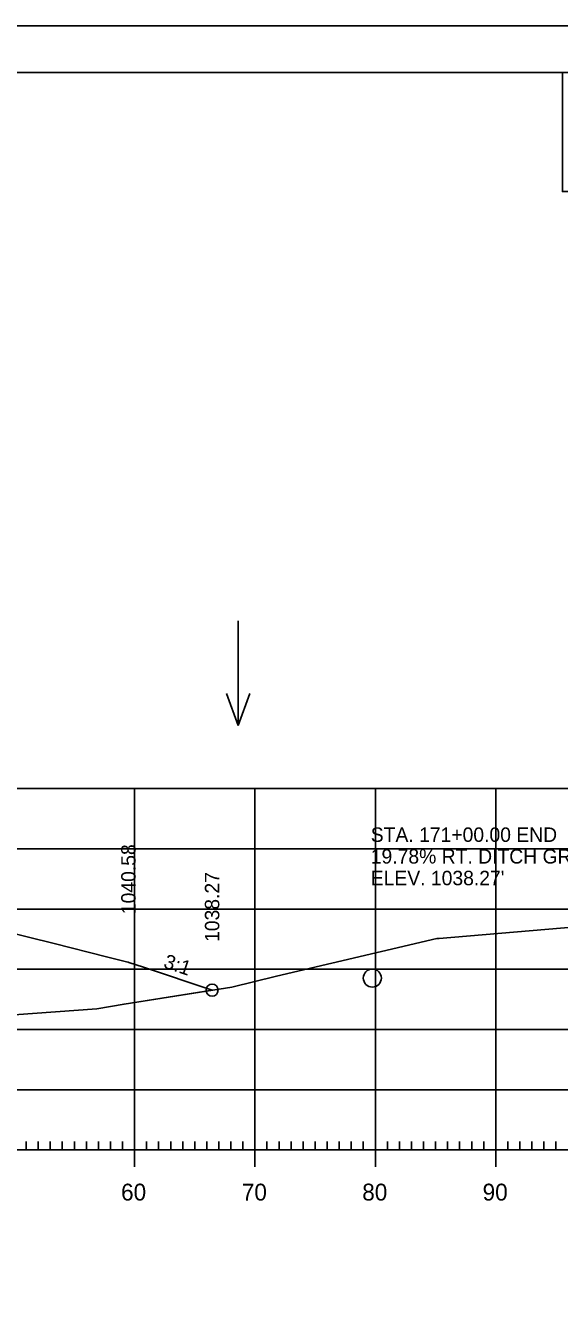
# Model space of a CAD drawing. Extents: x 1322838 to 1324533, y 339903 to 351025.
# Drawn here: x 1323754.7 to 1323799, y 347078.5 to 347185.2 of the extents above; entities that cross this region are included whole.
import ezdxf

# ---------------------------------------------------------------- set-up
doc = ezdxf.new("R2010")
doc.units = 0
for name, color, linetype in [('R_Axis', 7, 'Continuous'), ('R_Axis Annot', 7, 'Continuous'), ('R_Border', 7, 'Continuous'), ('R_Drive', 7, 'Continuous'), ('R_Exist Surface', 7, 'Continuous'), ('R_Fin Surface', 7, 'Continuous'), ('R_Fin Surface Annot', 7, 'Continuous'), ('R_Grid', 7, 'Continuous'), ('R_No Plot', 7, 'Continuous'), ('R_Water', 7, 'Continuous'), ('R_Water Annot', 7, 'Continuous')]:
    doc.layers.add(name, color=color, linetype=linetype)

msp = doc.modelspace()

# ---------------------------------------------------------------- linework, layer by layer
at = {"layer": 'R_Axis'}
for p, q in [((1323763.72, 347090.44), (1323763.72, 347093.24)), ((1323773.72, 347090.44), (1323773.72, 347093.24)), ((1323783.72, 347090.44), (1323783.72, 347093.24)), ((1323793.72, 347090.44), (1323793.72, 347093.24)), ((1323563.72, 347091.84), (1323843.72, 347091.84)), ((1323754.72, 347091.84), (1323754.72, 347092.54)), ((1323755.72, 347091.84), (1323755.72, 347092.54)), ((1323756.72, 347091.84), (1323756.72, 347092.54)), ((1323757.72, 347091.84), (1323757.72, 347092.54)), ((1323758.72, 347091.84), (1323758.72, 347092.54)), ((1323759.72, 347091.84), (1323759.72, 347092.54)), ((1323760.72, 347091.84), (1323760.72, 347092.54)), ((1323761.72, 347091.84), (1323761.72, 347092.54)), ((1323762.72, 347091.84), (1323762.72, 347092.54)), ((1323764.72, 347091.84), (1323764.72, 347092.54)), ((1323765.72, 347091.84), (1323765.72, 347092.54)), ((1323766.72, 347091.84), (1323766.72, 347092.54)), ((1323767.72, 347091.84), (1323767.72, 347092.54)), ((1323768.72, 347091.84), (1323768.72, 347092.54)), ((1323769.72, 347091.84), (1323769.72, 347092.54)), ((1323770.72, 347091.84), (1323770.72, 347092.54)), ((1323771.72, 347091.84), (1323771.72, 347092.54)), ((1323772.72, 347091.84), (1323772.72, 347092.54)), ((1323774.72, 347091.84), (1323774.72, 347092.54)), ((1323775.72, 347091.84), (1323775.72, 347092.54)), ((1323776.72, 347091.84), (1323776.72, 347092.54)), ((1323777.72, 347091.84), (1323777.72, 347092.54)), ((1323778.72, 347091.84), (1323778.72, 347092.54)), ((1323779.72, 347091.84), (1323779.72, 347092.54)), ((1323780.72, 347091.84), (1323780.72, 347092.54)), ((1323781.72, 347091.84), (1323781.72, 347092.54)), ((1323782.72, 347091.84), (1323782.72, 347092.54)), ((1323784.72, 347091.84), (1323784.72, 347092.54)), ((1323785.72, 347091.84), (1323785.72, 347092.54)), ((1323786.72, 347091.84), (1323786.72, 347092.54)), ((1323787.72, 347091.84), (1323787.72, 347092.54)), ((1323788.72, 347091.84), (1323788.72, 347092.54)), ((1323789.72, 347091.84), (1323789.72, 347092.54)), ((1323790.72, 347091.84), (1323790.72, 347092.54)), ((1323791.72, 347091.84), (1323791.72, 347092.54)), ((1323792.72, 347091.84), (1323792.72, 347092.54)), ((1323794.72, 347091.84), (1323794.72, 347092.54)), ((1323795.72, 347091.84), (1323795.72, 347092.54)), ((1323796.72, 347091.84), (1323796.72, 347092.54)), ((1323797.72, 347091.84), (1323797.72, 347092.54)), ((1323798.72, 347091.84), (1323798.72, 347092.54))]:
    msp.add_line(p, q, dxfattribs=at)
at = {"layer": 'R_Border'}
msp.add_line((1323545.72, 347181.3), (1323861.9, 347181.3), dxfattribs=at)
at = {"layer": 'R_Exist Surface'}
msp.add_lwpolyline([(1323753.73, 347103.06), (1323760.58, 347103.57), (1323762.85, 347103.95), (1323771.8, 347105.37), (1323775.52, 347106.27), (1323788.83, 347109.39), (1323788.96, 347109.4), (1323789.03, 347109.41), (1323801.69, 347110.47), (1323805.19, 347110.76), (1323814.73, 347111.56), (1323821.83, 347112.13), (1323831.75, 347112.89), (1323841.56, 347113.71), (1323843.72, 347113.89)], dxfattribs=at)
at = {"layer": 'R_Fin Surface'}
msp.add_lwpolyline([(1323750.5, 347110.6), (1323757.03, 347108.97), (1323761.4, 347107.87), (1323763.15, 347107.44), (1323763.21, 347107.42), (1323763.25, 347107.41), (1323764.46, 347107.01), (1323770.16, 347105.11)], dxfattribs=at)
at = {"layer": 'R_Grid'}
for p, q in [((1323563.72, 347121.84), (1323843.72, 347121.84)), ((1323763.72, 347091.84), (1323763.72, 347121.84)), ((1323773.72, 347091.84), (1323773.72, 347121.84)), ((1323783.72, 347091.84), (1323783.72, 347121.84)), ((1323793.72, 347091.84), (1323793.72, 347121.84)), ((1323563.72, 347116.84), (1323843.72, 347116.84)), ((1323563.72, 347111.84), (1323843.72, 347111.84)), ((1323563.72, 347106.84), (1323843.72, 347106.84)), ((1323563.72, 347101.84), (1323843.72, 347101.84)), ((1323563.72, 347096.84), (1323843.72, 347096.84)), ((1323563.72, 347091.84), (1323843.72, 347091.84))]:
    msp.add_line(p, q, dxfattribs=at)
at = {"layer": 'R_No Plot'}
msp.add_line((1323533.31, 347185.19), (1323866.65, 347185.19), dxfattribs=at)
for points in [[(1323533.31, 347185.19), (1323866.65, 347185.19), (1323866.65, 346971.86), (1323533.31, 346971.86)], [(1323779.64, 347181.3), (1323799.26, 347181.3), (1323799.26, 347171.42), (1323815.37, 347171.42), (1323838.57, 347171.42), (1323838.57, 347138.75), (1323861.77, 347138.75), (1323861.9, 346975.84), (1323545.72, 346975.84), (1323545.72, 347181.3)]]:
    msp.add_lwpolyline(points, close=True, dxfattribs=at)
msp.add_lwpolyline([(1323753.73, 347103.06), (1323760.58, 347103.57), (1323762.85, 347103.95), (1323770.16, 347105.11), (1323764.46, 347107.01), (1323763.25, 347107.41), (1323763.21, 347107.42), (1323763.15, 347107.44), (1323761.4, 347107.87), (1323757.03, 347108.97), (1323750.5, 347110.6)], dxfattribs=at)
msp.add_circle((1323770.16, 347105.11), 0.5, dxfattribs=at)
at = {"layer": 'R_Water'}
msp.add_circle((1323783.47, 347106.11), 0.75, dxfattribs=at)
at = {"layer": 'R_Water Annot'}
for p, q in [((1323772.33, 347135.77), (1323772.33, 347127.08)), ((1323772.33, 347127.08), (1323771.36, 347129.74)), ((1323772.33, 347127.08), (1323773.3, 347129.74))]:
    msp.add_line(p, q, dxfattribs=at)

# ---------------------------------------------------------------- texts
at = {"layer": 'R_Axis Annot'}
for s, p in [('60', (1323762.6, 347087.64)), ('70', (1323772.63, 347087.64)), ('80', (1323782.63, 347087.64)), ('90', (1323792.63, 347087.64))]:
    msp.add_text(s, height=1.4, dxfattribs=at).set_placement(p)
at = {"layer": 'R_Drive'}
for s, p in [('STA. 171+00.00 END', (1323783.34, 347117.42)), ('19.78% RT. DITCH GRADE', (1323783.34, 347115.62)), ("ELEV. 1038.27'", (1323783.34, 347113.82))]:
    msp.add_text(s, height=1.2, dxfattribs=at).set_placement(p)
at = {"layer": 'R_Fin Surface Annot'}
for s, rotation, p in [('1040.58', 90, (1323763.81, 347111.42)), ('1038.27', 90, (1323770.76, 347109.11)), ('1038.27', 90, (1323770.76, 347109.11)), ('3:1', 341.5635, (1323766.05, 347107))]:
    msp.add_text(s, height=1.2, rotation=rotation, dxfattribs=at).set_placement(p)

doc.saveas('drawing.dxf')
